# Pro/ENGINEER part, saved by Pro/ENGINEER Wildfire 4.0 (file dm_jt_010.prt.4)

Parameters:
  METRIC = "NO"

Other parameters: PITCH, DRILL_POINT_ANGLE, DRILL_DEPTH, DRILL_DIAMETER, THREAD_DIAMETER, THREADS_PER_INCH, THREAD_DEPTH, THREAD_LENGTH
